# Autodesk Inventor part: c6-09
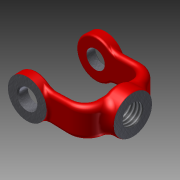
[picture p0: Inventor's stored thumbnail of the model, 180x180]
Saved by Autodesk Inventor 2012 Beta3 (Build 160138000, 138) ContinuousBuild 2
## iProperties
Created: 2010-12
Part Number: c6-09
Material: Cast Iron
Document SubType Name: Modeling
Designer: Beta-8540w
Mass: 107.693 g
Surface Area: 70.4564 cm^2
Volume: 14.8541 cm^3
Density: 7.25 g/cm^3
Author: Beta-8540w
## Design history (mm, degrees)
sketch "Sketch1"
  geometry: L1 (0, 0)-(0, -19.05); L2 (0, -19.05)-(-38.1, -19.05)
  constraints: 4 end point, 1 perpendicular, 1 vertical
  dimensions: "d0" = 19.05 distance of L1.start L1.end; "d1" = 38.1 distance of L1.end L2.end
workplane "Work Plane1"
sketch "Sketch2"
  geometry: C1 r 12.7 at (-38.1, 0); 2 further points
  constraints: 1 centre point, 1 coincident
  dimensions: "d2" = 25.4 diameter of C1
extrude "Extrusion1" new body sketch "Sketch2" distance "d3" = 7.62; taper "d4" = -2 deg
sketch "Sketch3"
  geometry: L1 (0, 0)-(7.66, 0); L2 (0, -9.525)-(-38.1, -9.525); L3 (-38.1, -9.525)-(-38.1, 9.525); L4 (-38.1, 9.525)-(0, 9.525); L5 (0, 9.525)-(0, -9.525); 3 further points
  constraints: 10 end point, 2 midpoint, 2 parallel, 1 coincident, 1 horizontal, 1 horizontal alignment, 1 perpendicular
  dimensions: "d11" = 19.05 distance of L4.end L2.start
extrude "Extrusion2" join sketch "Sketch3" distance "d12" = 4.7752; taper "d13" = 0 deg
sketch "Sketch4"
  geometry: L1 (29.7, 9.525)-(0, 9.525) reference; L2 (0, 9.525)-(0, -9.525) reference; L3 (0, -9.525)-(29.7, -9.525) reference; L4 (7.62, -9.525)-(7.62, 9.525); 1 further point
  constraints: 2 end point, 2 point on line, 1 perpendicular
  dimensions: "d14" = 7.62 distance between parallel lines of L2 L4
extrude "Extrusion3" join sketch "Sketch4" stored distance "d15" = 4.7752; taper "d16" = 0 deg
feature "FaceDraft1" dims angle "d17" = -2 deg
fillet "Fillet1" dims "d18" = 7.62
fillet "Fillet2" dims "d19" = 12.7
fillet "Fillet5" dims "d20" = 12.7
fillet "Fillet3"
fillet "Fillet4"
fillet "Fillet6" dims "d21" = 2.54
fillet "Fillet7" dims "d22" = 1.27
workplane "Work Plane2"
mirror "Mirror1"
sketch "Sketch5"
  geometry: C1 r 12.7 at (5.58, 11.125); 1 further point
  constraints: 1 centre point, 1 coincident
  dimensions: "d23" = 25.4 diameter of C1
extrude "Extrusion4" join sketch "Sketch5" distance "d24" = 6.35; taper "d25" = 0 deg; dims "d37" = 6.35, "d38" = 0
fillet "Fillet10" dims "d39" = 3.81
fillet "Fillet11" dims "d40" = 6.35
fillet "Fillet12" dims "d41" = 2.54
workplane "Work Plane4"
split "Split3"
split "Split1"
split "Split2"
hole "Hole2" diameter "d44" = 13.3858; stored, may be unused: countersink angle "d48" = 82 deg, drill point angle "d50" = 118 deg; dims "d45" = 19.05, "d46" = 9.525, "d47" = 6.35, "d49" = 25.4, "d69" = 25.4, "d70" = 25.4
hole "Hole3" diameter "d53" = 11.9126; stored, may be unused: countersink angle "d57" = 82 deg, drill point angle "d59" = 118 deg; dims "d54" = 19.05, "d55" = 9.525, "d56" = 9.2456, "d58" = 25.4, "d71" = 25.4, "d72" = 25.4
chamfer "Chamfer1" distance "d62" = 0.762; stored, may be unused: second distance "d63" = 3.175, angle "d64" = 45 deg
body "Solid1"
workplane "Work Plane3"
other parameters: "d67" = -1.27, "d68" = -1.27
